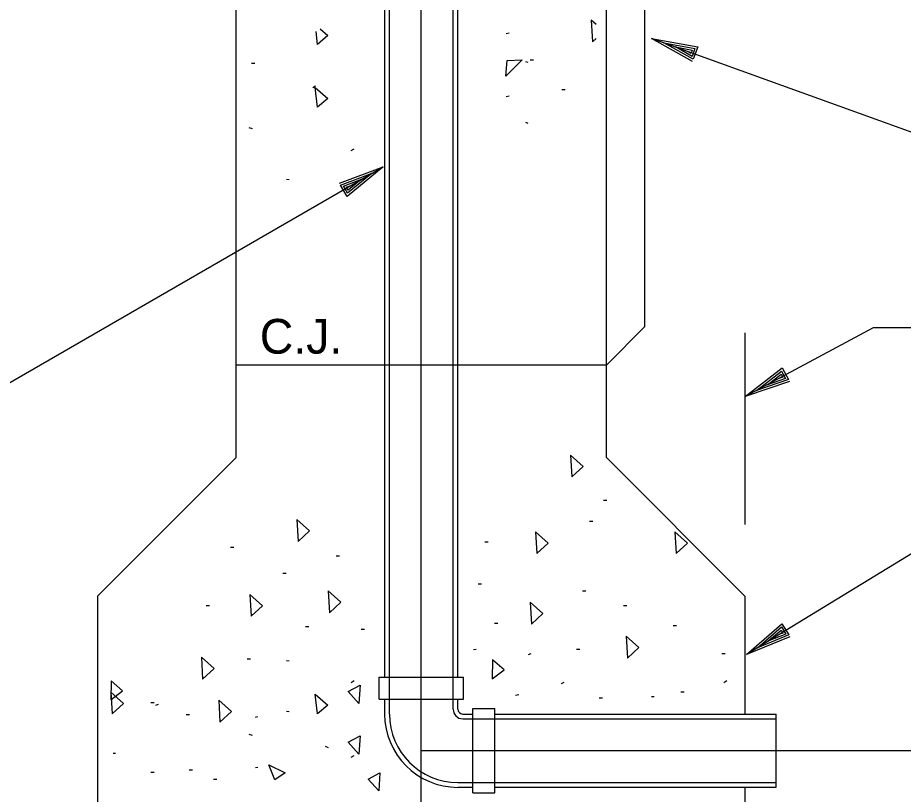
# Model space of a CAD drawing. Extents: x 22388.1 to 22405.7, y 22369.6 to 22390.4.
# Drawn here: x 22402.937 to 22404.133, y 22385.656 to 22386.705 of the extents above; entities that cross this region are included whole.
import ezdxf

# ---------------------------------------------------------------- set-up
doc = ezdxf.new("R2010")
doc.units = 0
for name, color, linetype in [('Level 1', 7, 'Continuous'), ('Level 2', 7, 'Continuous'), ('Level 4', 7, 'Continuous'), ('Level 44', 7, 'Continuous'), ('Level 7', 7, 'Continuous')]:
    doc.layers.add(name, color=color, linetype=linetype)

msp = doc.modelspace()

# ---------------------------------------------------------------- linework, layer by layer
at = {"layer": 'Level 1'}
for p, q in [((22403.482, 22383.7104), (22403.482, 22390.1172)), ((22403.9195, 22386.0209), (22403.9195, 22386.2795)), ((22403.8907, 22385.8075), (22403.8945, 22385.8098)), ((22403.482, 22385.7153), (22404.6015, 22385.7153))]:
    msp.add_line(p, q, dxfattribs=at)
at = {"layer": 'Level 2'}
for p, q in [((22403.4325, 22385.8146), (22403.4325, 22387.1543)), ((22403.4389, 22385.7644), (22403.4389, 22387.1543)), ((22403.525, 22385.7712), (22403.525, 22387.1543)), ((22403.5314, 22385.8146), (22403.5314, 22387.1543)), ((22403.7931, 22386.6771), (22403.7931, 22386.6771)), ((22403.8094, 22386.6712), (22403.8094, 22386.6712)), ((22403.4306, 22386.5039), (22403.4306, 22386.5039)), ((22403.4156, 22386.4952), (22403.4156, 22386.4952)), ((22403.732, 22386.2361), (22403.232, 22386.2361)), ((22403.9195, 22386.1934), (22403.9195, 22386.1934)), ((22403.9347, 22386.2016), (22403.9347, 22386.2016)), ((22403.9212, 22385.8453), (22403.9212, 22385.8453)), ((22403.936, 22385.8543), (22403.936, 22385.8543)), ((22403.425, 22385.8146), (22403.5389, 22385.8146)), ((22403.425, 22385.785), (22403.425, 22385.8146)), ((22403.5389, 22385.785), (22403.5389, 22385.8146)), ((22403.425, 22385.785), (22403.5389, 22385.785)), ((22403.4325, 22385.7647), (22403.4325, 22385.785)), ((22403.5314, 22385.7712), (22403.5314, 22385.785)), ((22403.5379, 22385.7647), (22403.5517, 22385.7647)), ((22403.5517, 22385.7722), (22403.5813, 22385.7722)), ((22403.5517, 22385.6583), (22403.5517, 22385.7722)), ((22403.5813, 22385.6583), (22403.5813, 22385.7722)), ((22403.5813, 22385.7647), (22403.9611, 22385.7647)), ((22403.9611, 22385.6658), (22403.9611, 22385.7647)), ((22403.5379, 22385.7583), (22403.9611, 22385.7583)), ((22403.5311, 22385.6722), (22403.9611, 22385.6722)), ((22403.5314, 22385.6658), (22403.5517, 22385.6658)), ((22403.5813, 22385.6658), (22403.9611, 22385.6658)), ((22403.5517, 22385.6583), (22403.5813, 22385.6583))]:
    msp.add_line(p, q, dxfattribs=at)
for points in [[(22404.5257, 22386.4448), (22404.4372, 22386.4448), (22403.7931, 22386.6771)], [(22403.8483, 22386.6462), (22403.7931, 22386.6771), (22403.8553, 22386.6657), (22403.8493, 22386.6491), (22403.8094, 22386.6712), (22403.8516, 22386.6634), (22403.8478, 22386.6528), (22403.8251, 22386.6656), (22403.848, 22386.6612), (22403.8464, 22386.6568), (22403.8414, 22386.6597)], [(22402.6622, 22386.1211), (22402.7677, 22386.1211), (22403.4306, 22386.5039)], [(22403.3714, 22386.4817), (22403.4306, 22386.5039), (22403.3818, 22386.4638), (22403.3729, 22386.4791), (22403.4156, 22386.4952), (22403.3824, 22386.468), (22403.3767, 22386.4778), (22403.4011, 22386.4869), (22403.3831, 22386.4722), (22403.3807, 22386.4763), (22403.3861, 22386.4782)], [(22404.1649, 22386.2865), (22404.0922, 22386.2865), (22403.9195, 22386.1934)], [(22403.9792, 22386.2139), (22403.9195, 22386.1934), (22403.9694, 22386.2321), (22403.9778, 22386.2165), (22403.9347, 22386.2016), (22403.9687, 22386.2279), (22403.974, 22386.2179), (22403.9494, 22386.2095), (22403.9679, 22386.2237), (22403.9701, 22386.2196), (22403.9647, 22386.2178)], [(22404.2757, 22386.0145), (22404.1984, 22386.0145), (22403.9212, 22385.8453)], [(22403.9798, 22385.8689), (22403.9212, 22385.8453), (22403.969, 22385.8866), (22403.9782, 22385.8715), (22403.936, 22385.8543), (22403.9685, 22385.8823), (22403.9744, 22385.8727), (22403.9502, 22385.863), (22403.968, 22385.8781), (22403.9704, 22385.8741), (22403.965, 22385.872)]]:
    msp.add_lwpolyline(points, dxfattribs=at)
msp.add_lwpolyline([(22403.5777, 22385.8122), (22403.5937, 22385.8243), (22403.5783, 22385.8379)], close=True, dxfattribs=at)
for centre, radius in [((22403.5314, 22385.7647), 0.099), ((22403.5314, 22385.7647), 0.0925), ((22403.5379, 22385.7712), 0.0129), ((22403.5379, 22385.7712), 0.00645)]:
    msp.add_arc(centre, radius, 180, 270, dxfattribs=at)
at = {"layer": 'Level 44'}
for p, q in [((22403.5965, 22386.6839), (22403.6008, 22386.6847)), ((22403.6292, 22386.6483), (22403.6335, 22386.6483)), ((22403.2526, 22386.6439), (22403.2571, 22386.6439)), ((22403.6226, 22386.6462), (22403.6259, 22386.6449)), ((22403.3353, 22386.6109), (22403.339, 22386.6131)), ((22403.5965, 22386.5989), (22403.6008, 22386.5997)), ((22403.6716, 22386.608), (22403.6761, 22386.608)), ((22403.6226, 22386.5639), (22403.6259, 22386.5627)), ((22403.249, 22386.5567), (22403.2535, 22386.5554)), ((22403.3874, 22386.5259), (22403.3911, 22386.5281)), ((22403.3, 22386.4869), (22403.3037, 22386.4865)), ((22403.7281, 22386.0535), (22403.7326, 22386.0535)), ((22403.7093, 22386.0253), (22403.7138, 22386.0253)), ((22403.2244, 22385.9901), (22403.2289, 22385.9901)), ((22403.568, 22385.9971), (22403.5725, 22385.9971)), ((22403.3668, 22385.9783), (22403.3713, 22385.9783)), ((22403.295, 22385.9548), (22403.2995, 22385.9548)), ((22403.5588, 22385.9405), (22403.5633, 22385.9405)), ((22403.6999, 22385.9311), (22403.7044, 22385.9311)), ((22403.1915, 22385.9112), (22403.196, 22385.9112)), ((22403.7551, 22385.9111), (22403.7596, 22385.9111)), ((22403.3256, 22385.8829), (22403.3301, 22385.8829)), ((22403.5809, 22385.8876), (22403.5854, 22385.8876)), ((22403.8221, 22385.8841), (22403.8266, 22385.8841)), ((22403.4009, 22385.8794), (22403.4054, 22385.8794)), ((22403.5526, 22385.852), (22403.5559, 22385.8522)), ((22403.6266, 22385.8449), (22403.6302, 22385.8466)), ((22403.6915, 22385.8523), (22403.696, 22385.8523)), ((22403.888, 22385.8464), (22403.8925, 22385.8464)), ((22403.2468, 22385.8394), (22403.2513, 22385.8394)), ((22403.3, 22385.8369), (22403.3037, 22385.8366)), ((22403.3874, 22385.8075), (22403.3911, 22385.8098)), ((22403.6714, 22385.8059), (22403.6749, 22385.8076)), ((22403.6094, 22385.7903), (22403.6137, 22385.791)), ((22403.7222, 22385.7864), (22403.7267, 22385.7864)), ((22403.7928, 22385.7885), (22403.7965, 22385.7882)), ((22403.8327, 22385.7946), (22403.8372, 22385.7946)), ((22403.1167, 22385.7805), (22403.1212, 22385.7805)), ((22403.1233, 22385.7765), (22403.1269, 22385.7782)), ((22403.1644, 22385.764), (22403.1689, 22385.764)), ((22403.258, 22385.7607), (22403.2613, 22385.7613)), ((22403.3, 22385.7685), (22403.3037, 22385.7682)), ((22403.249, 22385.7374), (22403.2535, 22385.7362)), ((22403.3523, 22385.7214), (22403.3563, 22385.7194)), ((22403.0657, 22385.7118), (22403.069, 22385.712)), ((22403.3874, 22385.7066), (22403.3911, 22385.7088)), ((22403.1683, 22385.6894), (22403.1728, 22385.6894)), ((22403.258, 22385.6923), (22403.2613, 22385.6928)), ((22403.1167, 22385.6863), (22403.1212, 22385.6863)), ((22403.2013, 22385.6769), (22403.2058, 22385.6769))]:
    msp.add_line(p, q, dxfattribs=at)
for points in [[(22403.7181, 22386.6961), (22403.7116, 22386.7019), (22403.7133, 22386.6724)], [(22403.3455, 22386.6901), (22403.3559, 22386.681), (22403.3417, 22386.6691), (22403.3398, 22386.6864)], [(22403.7133, 22386.6724), (22403.7181, 22386.6769)]]:
    msp.add_lwpolyline(points, dxfattribs=at)
for points in [[(22403.598, 22386.6472), (22403.618, 22386.6483), (22403.5963, 22386.6261)], [(22403.3388, 22386.6109), (22403.3559, 22386.596), (22403.3417, 22386.5841)], [(22403.6851, 22386.085), (22403.7005, 22386.0992), (22403.6834, 22386.1145)], [(22403.3156, 22385.9979), (22403.331, 22386.0122), (22403.3139, 22386.0274)], [(22403.6381, 22385.9814), (22403.6535, 22385.9956), (22403.6364, 22386.0109)], [(22403.8262, 22385.9814), (22403.8416, 22385.9956), (22403.8245, 22386.0109)], [(22403.3579, 22385.9014), (22403.3733, 22385.9156), (22403.3563, 22385.9309)], [(22403.252, 22385.8967), (22403.2675, 22385.9109), (22403.2504, 22385.9262)], [(22403.6309, 22385.8861), (22403.6463, 22385.9003), (22403.6292, 22385.9156)], [(22403.7603, 22385.8402), (22403.7758, 22385.8544), (22403.7587, 22385.8697)], [(22403.1865, 22385.8119), (22403.202, 22385.8262), (22403.1849, 22385.8414)], [(22403.0625, 22385.7839), (22403.0785, 22385.796), (22403.0632, 22385.8096)], [(22403.3975, 22385.779), (22403.3833, 22385.795), (22403.3992, 22385.8035)], [(22403.0643, 22385.7648), (22403.0797, 22385.7791), (22403.0626, 22385.7943)], [(22403.3388, 22385.7917), (22403.3559, 22385.7768), (22403.3417, 22385.7648)], [(22403.21, 22385.7538), (22403.2254, 22385.7681), (22403.2083, 22385.7833)], [(22403.3975, 22385.7106), (22403.3833, 22385.7266), (22403.3992, 22385.7351)], [(22403.2841, 22385.6758), (22403.2762, 22385.6963), (22403.2983, 22385.6855)], [(22403.4244, 22385.6608), (22403.4101, 22385.6768), (22403.426, 22385.6853)]]:
    msp.add_lwpolyline(points, close=True, dxfattribs=at)
at = {"layer": 'Level 7'}
for p, q in [((22403.232, 22386.1111), (22403.232, 22387.2585)), ((22403.732, 22386.1111), (22403.732, 22387.2585)), ((22403.7841, 22386.2882), (22403.7841, 22386.8835)), ((22403.732, 22386.2361), (22403.7841, 22386.2882)), ((22403.232, 22386.1111), (22403.0451, 22385.9242)), ((22403.732, 22386.1111), (22403.9195, 22385.9236)), ((22403.0451, 22384.1736), (22403.0451, 22385.9242)), ((22403.9195, 22385.7647), (22403.9195, 22385.9236)), ((22403.9195, 22384.1736), (22403.9195, 22385.6658))]:
    msp.add_line(p, q, dxfattribs=at)

# ---------------------------------------------------------------- texts
at = {"layer": 'Level 4'}
msp.add_text('C.J.', height=0.04688, dxfattribs=at).set_placement((22403.2638, 22386.2514))

doc.saveas('drawing.dxf')
